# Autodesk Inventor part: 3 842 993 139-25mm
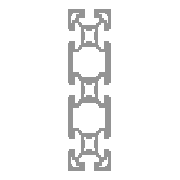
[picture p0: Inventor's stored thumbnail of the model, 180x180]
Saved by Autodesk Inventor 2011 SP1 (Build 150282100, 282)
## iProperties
Category: End -/-
Created: 2011-02
Part Number: 3 842 993 139-25mm
Document SubType Name: Modeling
Designer: SRW
Density: 2.71 g/cm^3
Categories: <MemberInstance><Categories><Category DisplayName="Structural Shapes" InternalName="089c4875-fa83-4c05-b084-43b9cc11f5ed" Mnemonic="GRDR"><CategoryParameter Dis
Stock Number: 3 842 993 139
Description: PROFILE 40x120, -/-
Material: Aluminum-6061
Mass: 104.507 g
Surface Area: 316.819 cm^2
Volume: 38.5633 cm^3
G_L: 25.000 mm
Author: SRW
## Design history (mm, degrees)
node "Blocks"
  sketch "40x120"
    geometry: L1 (61.954, 105.258)-(61.954, 106.047); L2 (61.454, 97.597)-(61.454, 92.547); L3 (62.954, 99.297)-(62.954, 97.047); L4 (61.954, 99.297)-(62.954, 99.297); L5 (65.954, 92.547)-(65.954, 93.347); L6 (61.454, 92.547)-(65.954, 92.547); L7 (65.954, 97.047)-(65.954, 102.047); L8 (65.954, 102.047)-(65.166, 102.047); L9 (56.954, 103.047)-(59.204, 103.047); L10 (39.954, 93.632)-(39.954, 81.461); L11 (53.54, 95.047)-(41.368, 95.047); L12 (54.954, 81.461)-(54.954, 93.632); L13 (53.54, 80.047)-(41.368, 80.047); L14 (49.852, 82.047)-(52.954, 82.047); L15 (41.954, 82.047)-(45.056, 82.047); L16 (45.056, 82.047)-(45.456, 82.963); L17 (49.453, 82.963)-(49.852, 82.047); L18 (41.954, 85.149)-(41.954, 82.047); L19 (52.954, 82.047)-(52.954, 85.149); L20 (42.871, 85.548)-(41.954, 85.149); L21 (52.954, 85.149)-(52.038, 85.548); L22 (52.038, 89.545)-(52.954, 89.944); L23 (41.954, 89.944)-(42.871, 89.545); L24 (52.954, 89.944)-(52.954, 93.047); L25 (52.954, 93.047)-(49.852, 93.047); L26 (49.852, 93.047)-(49.453, 92.13); L27 (45.456, 92.13)-(45.056, 93.047); L28 (45.056, 93.047)-(41.954, 93.047); L29 (41.954, 93.047)-(41.954, 89.944); L30 (35.99, 57.597)-(39.954, 53.632); L31 (33.454, 57.597)-(35.99, 57.597); L32 (33.454, 52.547)-(33.454, 57.597); L33 (28.954, 52.547)-(33.454, 52.547); L34 (28.954, 53.347)-(28.954, 52.547); L35 (27.454, 53.347)-(28.954, 53.347); L36 (27.454, 61.547)-(27.454, 53.347); L37 (28.454, 61.547)-(27.454, 61.547); L38 (28.454, 73.547)-(28.454, 61.547); L39 (27.454, 73.547)-(28.454, 73.547); L40 (27.454, 81.747)-(27.454, 73.547); L41 (28.954, 81.747)-(27.454, 81.747); L42 (28.954, 82.547)-(28.954, 81.747); L43 (41.366, 56.468)-(53.543, 56.468); L44 (41.368, 80.047)-(37.028, 75.706); L45 (39.954, 81.461)-(35.99, 77.497); L46 (35.99, 77.497)-(33.454, 77.497); L47 (33.454, 77.497)-(33.454, 82.547); L48 (33.454, 82.547)-(28.954, 82.547); L49 (37.028, 60.806)-(41.366, 56.468); L50 (31.457, 60.806)-(37.028, 60.806); L51 (31.457, 75.706)-(31.457, 60.806); L52 (37.028, 75.706)-(31.457, 75.706); L53 (52.954, 49.944)-(52.954, 53.047); L54 (57.88, 75.706)-(53.54, 80.047); L55 (53.543, 56.468)-(57.88, 60.806); L56 (58.918, 77.497)-(54.954, 81.461); L57 (54.954, 53.632)-(58.918, 57.597); L58 (61.454, 77.497)-(58.918, 77.497); L59 (58.918, 57.597)-(61.454, 57.597); L60 (57.88, 60.806)-(63.452, 60.806); L61 (63.452, 60.806)-(63.452, 75.706); L62 (61.454, 57.597)-(61.454, 52.547); L63 (65.954, 52.547)-(65.954, 53.347); L64 (61.454, 52.547)-(65.954, 52.547)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; A1 r 0.5 centre (62.454, 105.258) between (61.954, 105.258) and (62.377, 104.764); A2 r 2.75 centre (61.954, 102.047) between (64.672, 102.47) and (62.377, 104.764); A3 r 0.5 centre (65.166, 102.547) between (64.672, 102.47) and (65.166, 102.047); A4 r 1.5 centre (64.454, 97.047) between (62.954, 97.047) and (65.954, 97.047); A5 r 5 centre (47.454, 87.547) between (45.456, 82.963) and (49.453, 82.963); A6 r 5 centre (47.454, 87.547) between (52.038, 85.548) and (52.038, 89.545); A7 r 5 centre (47.454, 87.547) between (42.871, 89.545) and (42.871, 85.548); A8 r 5 centre (47.454, 87.547) between (49.453, 92.13) and (45.456, 92.13); A9 r 5 centre (47.454, 47.547) between (45.456, 42.963) and (49.453, 42.963); A10 r 5 centre (47.454, 47.547) between (42.871, 49.545) and (42.871, 45.548); A11 r 5 centre (47.454, 47.547) between (52.038, 45.548) and (52.038, 49.545); A12 r 5 centre (47.454, 47.547) between (49.453, 52.13) and (45.456, 52.13); A13 r 1.5 centre (30.454, -1.953) between (31.954, -1.953) and (28.954, -1.953); A14 r 1.5 centre (37.954, -9.453) between (37.954, -10.953) and (37.954, -7.953); A15 r 2.75 centre (32.954, -6.953) between (35.704, -6.953) and (32.954, -4.203); A16 r 0.5 centre (29.743, -7.453) between (30.237, -7.377) and (29.743, -6.953); A17 r 0.5 centre (32.454, -10.165) between (32.954, -10.165) and (32.531, -9.671); A18 r 2.75 centre (32.954, -6.953) between (30.237, -7.377) and (32.531, -9.671); A19 r 0.5 centre (32.454, 105.258) between (32.531, 104.764) and (32.954, 105.258); A20 r 3 centre (30.454, 104.547) between (30.454, 107.547) and (27.454, 104.547); A21 r 1.5 centre (37.954, 104.547) between (37.954, 103.047) and (37.954, 106.047); A22 r 2.75 centre (32.954, 102.047) between (32.531, 104.764) and (30.237, 102.47); A23 r 5 centre (47.454, 7.547) between (42.871, 9.545) and (42.871, 5.548); A24 r 5 centre (47.454, 7.547) between (52.038, 5.548) and (52.038, 9.545); A25 r 5 centre (47.454, 7.547) between (49.453, 12.13) and (45.456, 12.13); A26 r 5 centre (47.454, 7.547) between (45.456, 2.963) and (49.453, 2.963); A27 r 3 centre (64.454, -9.453) between (64.454, -12.453) and (67.454, -9.453); A28 r 1.5 centre (64.454, -1.953) between (65.954, -1.953) and (62.954, -1.953); A29 r 2.75 centre (61.954, -6.953) between (61.954, -4.203) and (59.204, -6.953); A30 r 0.5 centre (65.166, -7.453) between (65.166, -6.953) and (64.672, -7.377); A31 r 0.5 centre (62.454, -10.165) between (62.377, -9.671) and (61.954, -10.165); A32 r 2.75 centre (61.954, -6.953) between (62.377, -9.671) and (64.672, -7.377); A33 r 1.5 centre (56.954, -9.453) between (56.954, -7.953) and (56.954, -10.953); A34 r 3 centre (30.454, -9.453) between (27.454, -9.453) and (30.454, -12.453); A35 r 0.5 centre (29.743, 102.547) between (29.743, 102.047) and (30.237, 102.47); A36 r 2.75 centre (32.954, 102.047) between (32.954, 99.297) and (35.704, 102.047); A37 r 1.5 centre (30.454, 97.047) between (28.954, 97.047) and (31.954, 97.047); A38 r 3 centre (64.454, 104.547) between (67.454, 104.547) and (64.454, 107.547); A39 r 1.5 centre (56.954, 104.547) between (56.954, 106.047) and (56.954, 103.047); A40 r 2.75 centre (61.954, 102.047) between (59.204, 102.047) and (61.954, 99.297); 1 further point
    constraints: 472 end point, 80 point on circle, 40 centre point
node "Start Plane"
node "End Plane"
sketch "Sketch1"
  geometry: 1 further point
  constraints: 1 other
extrude "Body" new body sketch "Sketch1" stored distance "d4" = 0.13; taper "d5" = 0 deg
node "Driven Length"
  sketch "Sketch55"
    geometry: L1 (0, 0)-(10, 0) reference
    constraints: 2 end point, 1 horizontal
  workplane "Work Plane24"
  sketch "Sketch56"
    geometry: L1 (-28, 0)-(28, 0) reference; L2 (-28, 25)-(28, 25) reference
    dimensions: "d7" = 25 distance between parallel lines of L1 L2 (derived)
sketch "Sketch9"
  geometry: 3 further points
  constraints: 2 vertical alignment
  dimensions: "d88" = 40 distance of point (0, 0) point (0, -40); "d100" = 40 distance of point (0, -80) point (0, -40) (= d88)
hole "M12/-" sketch "Sketch9" at (0, 0), (0, -40), (0, -80) diameter "d17" = 10.106; stored, may be unused: countersink angle "d21" = 90 deg, drill point angle "d23" = 118 deg; dims "d18" = 6, "d19" = 4, "d20" = 2, "d22" = 55
sketch "Sketch10"
  geometry: 3 further points
  constraints: 2 vertical alignment
  dimensions: "d89" = 40 distance of point (0, 0) point (0, -40); "d101" = 40 distance of point (0, -40) point (0, -80) (= d89)
hole "-/M12" sketch "Sketch10" at (0, 0), (0, -40), (0, -80) diameter "d24" = 10.106; stored, may be unused: countersink angle "d28" = 90 deg, drill point angle "d30" = 118 deg; dims "d25" = 6, "d26" = 4, "d27" = 2, "d29" = 55
sketch "Sketch11"
  geometry: L1 (-13.7, 0)-(12.2, 0) reference; C1 r 8.5 at (0, 20); 1 further point
  constraints: 1 centre point, 1 vertical alignment
  dimensions: "d31" = 20 distance from line of C1.centre L1; "d32" = 17 diameter of C1
extrude "D17VS/-" cut sketch "Sketch11" stored distance "d33" = 10; taper "d34" = 0 deg
sketch "Sketch12"
  geometry: L1 (-13.7, 25)-(12.2, 25) reference; C1 r 8.5 at (0, 5); 1 further point
  constraints: 1 centre point, 1 vertical alignment
  dimensions: "d35" = 17 diameter of C1; "d36" = 20 distance from line of L1 C1.centre
extrude "-/D17VS" cut sketch "Sketch12" stored distance "d37" = 10; taper "d38" = 0 deg
sketch "Sketch13"
  geometry: L1 (-12.98, 0)-(7.88, 0) reference; C1 r 4.9 at (0, 20); 1 further point
  constraints: 1 centre point, 1 vertical alignment
  dimensions: "d39" = 9.8 diameter of C1; "d40" = 20 distance from line of C1.centre L1
extrude "D9.8VS/-" cut sketch "Sketch13" stored distance "d41" = 10; taper "d42" = 0 deg
sketch "Sketch14"
  geometry: L1 (-12.98, 25)-(7.88, 25) reference; C1 r 4.9 at (0, 5); 1 further point
  constraints: 1 centre point, 1 vertical alignment
  dimensions: "d43" = 9.8 diameter of C1; "d44" = 20 distance from line of L1 C1.centre
extrude "-/D9.8VS" cut sketch "Sketch14" stored distance "d45" = 10; taper "d46" = 0 deg
sketch "Sketch15"
  geometry: L1 (-102.86, 25)-(22.86, 25) reference; C1 r 4.9 at (0, 5); C2 r 4.9 at (-40, 5); C3 r 4.9 at (-80, 5); 1 further point
  constraints: 3 centre point, 2 equal radius, 2 horizontal alignment, 1 vertical alignment
  dimensions: "d47" = 9.8 diameter of C1; "d48" = 20 distance from line of L1 C1.centre; "d92" = 40 distance of C1.centre C2.centre; "d102" = 40 distance of C2.centre C3.centre (= d92)
extrude "-/D9.8" cut sketch "Sketch15" stored distance "d49" = 10; taper "d50" = 0 deg
sketch "Sketch26"
  geometry: L1 (-102.86, 0)-(22.86, 0) reference; C1 r 4.9 at (0, 20); C2 r 4.9 at (-40, 20); C3 r 4.9 at (-80, 20); 1 further point
  constraints: 3 centre point, 2 equal radius, 2 horizontal alignment, 1 vertical alignment
  dimensions: "d62" = 9.8 diameter of C1; "d65" = 20 distance from line of L1 C1.centre; "d93" = 40 distance of C1.centre C2.centre; "d103" = 40 distance of C2.centre C3.centre (= d93)
extrude "D9.8/-" cut sketch "Sketch26" stored distance "d63" = 10; taper "d64" = 0 deg
sketch "Sketch37"
  geometry: L1 (-107.9, 0)-(27.9, 0) reference; L2 (-107.9, 25)-(27.9, 25) reference; C1 r 8.5 at (0, 20); C2 r 8.5 at (-40, 20); C3 r 8.5 at (-80, 20); 1 further point
  constraints: 3 centre point, 2 equal radius, 2 horizontal alignment, 1 vertical alignment
  dimensions: "d76" = 20 distance from line of C1.centre L1; "d77" = 17 diameter of C1; "d90" = 40 distance of C1.centre C2.centre; "d104" = 40 distance of C2.centre C3.centre (= d90)
extrude "D17/-" cut sketch "Sketch37" stored distance "d78" = 10; taper "d79" = 0 deg
sketch "Sketch38"
  geometry: L1 (-107.9, 25)-(27.9, 25) reference; C1 r 8.5 at (0, 5); C2 r 8.5 at (-40, 5); C3 r 8.5 at (-80, 5); 1 further point
  constraints: 3 centre point, 2 equal radius, 2 horizontal alignment, 1 vertical alignment
  dimensions: "d80" = 17 diameter of C1; "d81" = 20 distance from line of L1 C1.centre; "d91" = 40 distance of C1.centre C2.centre; "d105" = 40 distance of C2.centre C3.centre (= d91)
extrude "-/D17" cut sketch "Sketch38" stored distance "d82" = 10; taper "d83" = 0 deg
body "Solid1"
node "40x120:1"
other parameters: "Length" = 25, "G_OFFSET_START" = 0 [user parameter; used in 2 equation terms], "G_OFFSET_END" = 0 [user parameter; used in 2 equation terms], "d2" = 0 (computed from G_OFFSET_START), "d3" = 25 (= Length + G_OFFSET_END), "G_L" = 25 (= d7) [user parameter], "Length2" = 25 (= G_OFFSET_START + Length + G_OFFSET_END) [user parameter], "d112" = 90 deg
